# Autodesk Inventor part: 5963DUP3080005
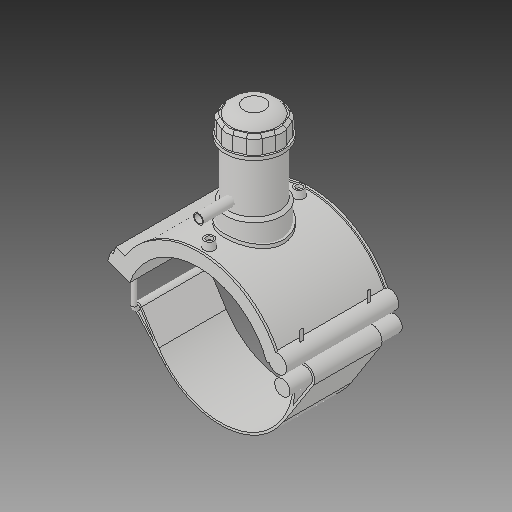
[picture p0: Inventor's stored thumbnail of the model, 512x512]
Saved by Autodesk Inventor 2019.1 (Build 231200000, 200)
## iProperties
Created: 2017-07
Part Number: 5963DUP3080005
Material: Generic
Description: PLASSON TAPPING SADDLE 8''DIPS x 1/2''CTS
Document SubType Name: Modeling
Designer: KIM
Density: 1 g/cm^3
Appearance: Default
Author: KIM
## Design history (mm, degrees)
derived "5963DBP_5963BUP.ipt"
feature "Solid1::5963DBP_5963BUP.ipt"
feature "Solid2::5963DBP_5963BUP.ipt"
feature "Solid3::5963DBP_5963BUP.ipt"
tag "TaggingFeature1"
body "Solid1"
body "Solid2"
body "Solid3"
other parameters: "d0" = 228.9, "d2" = 269.748, "d3" = 57.225, "d4" = 176.022, "d5" = 0, "d6" = 0.1, "d8" = 0, "d19" = 6, "d20" = 6, "d21" = 105.6132, "d23" = 0, "d24" = 52.8066, "d26" = 0, "d27" = 3, "d28" = 3, "d29" = 3, "d30" = 76.3, "d31" = 6, "d32" = 0, "d33" = 0, "d34" = 0.6, "d40" = 138.07248, "d41" = 91.56, "d43" = 0, "d45" = 0, "d47" = 238.3752, "d70" = 15, "d72" = 0, "d73" = 6, "d75" = 5, "d76" = 0, "d77" = 11.445, "d78" = 144.45, "d79" = 15, "d80" = 70.4088, "d82" = 5 deg, "d84" = 4, "d85" = 14, "d86" = 0, "d87" = 3, "d88" = 0, "d89" = 1, "d90" = 1, "d91" = 140.8176, "d92" = 0, "d93" = 0.5, "d94" = 120.47368, "d96" = 270.83448, "d97" = 3.52044, "d98" = 0, "d120" = 140 deg, "d121" = 24.228, "d122" = 20 deg, "d123" = 531.048, "d124" = 159.3144, "d126" = 0, "d143" = 235.767, "d145" = 28.17231, "d149" = 3.4335, "d150" = 30.98954, "d153" = 176.022, "d154" = 0, "d156" = 132.762, "d157" = 160 deg, "d159" = 7.3248, "d161" = 3.4335, "d162" = 105.6132, "d163" = 0, "d164" = 114.45, "d167" = 22.89, "d168" = 129.5239, "d170" = 3.4335, "d172" = 0, "d173" = 1, "d175" = 114.45, "d176" = 20 deg, "d177" = 16.023, "d178" = 36.624, "d180" = 0, "d183" = 14.6496, "d184" = 12.8184, "d185" = 57.20715, "d186" = 57.20715, "d187" = 132.762, "d188" = 10.9872, "d189" = 16.023, "d190" = 0, "d191" = 199.143, "d193" = 7.3248, "d194" = 6.16077, "d195" = 90 deg, "d197" = 0, "d199" = 0, "d200" = 18.312, "d202" = 0, "d203" = 177.038, "d204" = 86.982, "d205" = 64.092, "d206" = 77.826, "d207" = 132.7785, "d208" = 138.08964, "d209" = 164.64534, "d210" = 78.7416, "d211" = 91.56, "d212" = 73.248, "d213" = 51.4116, "d216" = 0, "d217" = 22.89, "d218" = 22.89, "d219" = 4.578, "d222" = 228.9, "d224" = 0, "d225" = 65.024, "d226" = 15.8, "d227" = 12.64, "d228" = 87.376, "d230" = 4.578, "d_" = 228.9, "B_" = 179.832, "L_" = 176.022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
